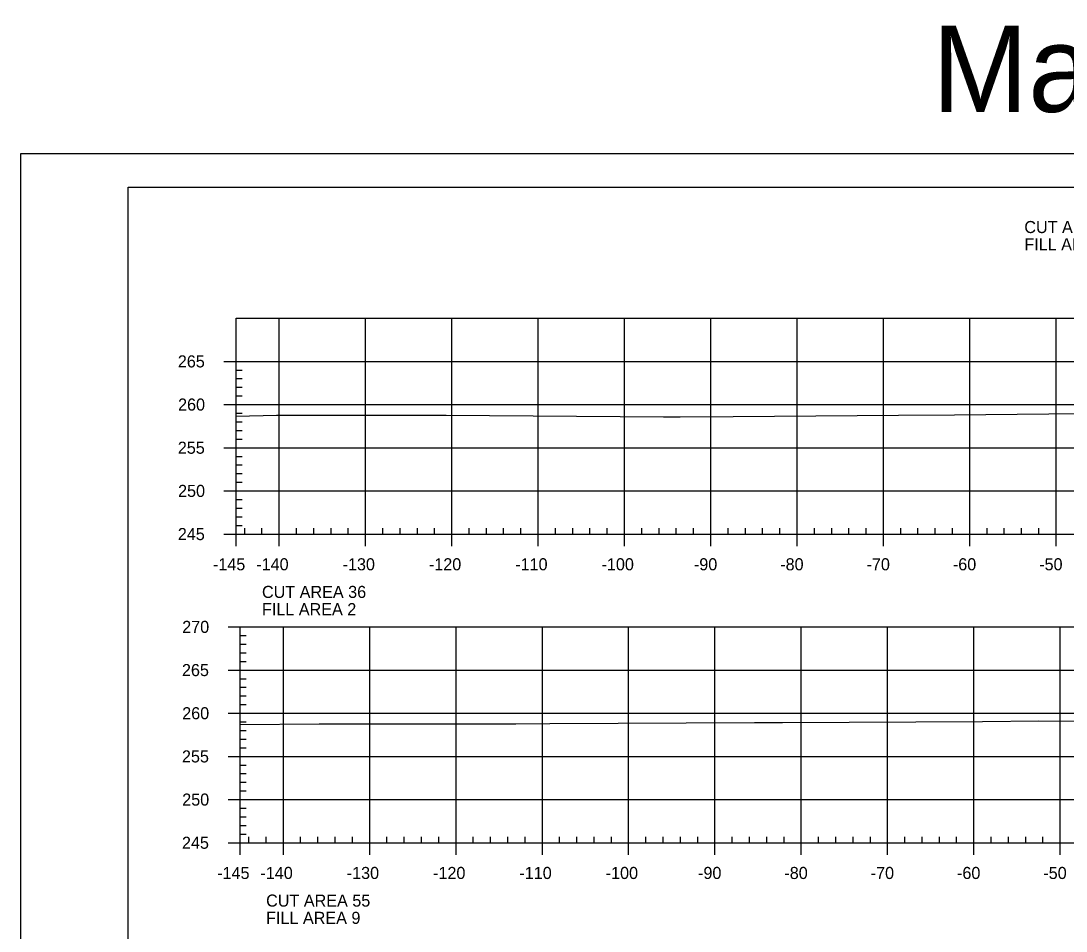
# Model space of a CAD drawing. Extents: x 1365647 to 1367999, y 387113 to 400173.
# Drawn here: x 1366507.4 to 1366628.5, y 387249 to 387354.4 of the extents above; entities that cross this region are included whole.
import ezdxf

# ---------------------------------------------------------------- set-up
doc = ezdxf.new("R2010")
doc.units = 0
for name, color, linetype in [('R_Axis', 7, 'Continuous'), ('R_Axis Annot', 7, 'Continuous'), ('R_Border', 7, 'Continuous'), ('R_Drive', 7, 'Continuous'), ('R_Exist Surface', 7, 'Continuous'), ('R_Grid', 7, 'Continuous'), ('R_No Plot', 7, 'Continuous')]:
    doc.layers.add(name, color=color, linetype=linetype)

msp = doc.modelspace()

# ---------------------------------------------------------------- linework, layer by layer
at = {"layer": 'R_Axis'}
for p, q in [((1366530.92, 387315.01), (1366532.32, 387315.01)), ((1366532.32, 387295.01), (1366532.32, 387315.01)), ((1366532.32, 387314.01), (1366533.02, 387314.01)), ((1366532.32, 387313.01), (1366533.02, 387313.01)), ((1366532.32, 387312.01), (1366533.02, 387312.01)), ((1366532.32, 387311.01), (1366533.02, 387311.01)), ((1366530.92, 387310.01), (1366532.32, 387310.01)), ((1366532.32, 387309.01), (1366533.02, 387309.01)), ((1366532.32, 387308.01), (1366533.02, 387308.01)), ((1366532.32, 387307.01), (1366533.02, 387307.01)), ((1366532.32, 387306.01), (1366533.02, 387306.01)), ((1366530.92, 387305.01), (1366532.32, 387305.01)), ((1366532.32, 387304.01), (1366533.02, 387304.01)), ((1366532.32, 387303.01), (1366533.02, 387303.01)), ((1366532.32, 387302.01), (1366533.02, 387302.01)), ((1366532.32, 387301.01), (1366533.02, 387301.01)), ((1366530.92, 387300.01), (1366532.32, 387300.01)), ((1366532.32, 387299.01), (1366533.02, 387299.01)), ((1366532.32, 387298.01), (1366533.02, 387298.01)), ((1366532.32, 387297.01), (1366533.02, 387297.01)), ((1366532.32, 387296.01), (1366533.02, 387296.01)), ((1366530.92, 387295.01), (1366532.32, 387295.01)), ((1366532.32, 387295.01), (1366532.32, 387295.71)), ((1366532.32, 387295.01), (1366822.32, 387295.01)), ((1366532.32, 387293.61), (1366532.32, 387295.01)), ((1366533.32, 387295.01), (1366533.32, 387295.71)), ((1366535.32, 387295.01), (1366535.32, 387295.71)), ((1366537.32, 387293.61), (1366537.32, 387295.01)), ((1366539.32, 387295.01), (1366539.32, 387295.71)), ((1366541.32, 387295.01), (1366541.32, 387295.71)), ((1366543.32, 387295.01), (1366543.32, 387295.71)), ((1366545.32, 387295.01), (1366545.32, 387295.71)), ((1366547.32, 387293.61), (1366547.32, 387295.01)), ((1366549.32, 387295.01), (1366549.32, 387295.71)), ((1366551.32, 387295.01), (1366551.32, 387295.71)), ((1366553.32, 387295.01), (1366553.32, 387295.71)), ((1366555.32, 387295.01), (1366555.32, 387295.71)), ((1366557.32, 387293.61), (1366557.32, 387295.01)), ((1366559.32, 387295.01), (1366559.32, 387295.71)), ((1366561.32, 387295.01), (1366561.32, 387295.71)), ((1366563.32, 387295.01), (1366563.32, 387295.71)), ((1366565.32, 387295.01), (1366565.32, 387295.71)), ((1366567.32, 387293.61), (1366567.32, 387295.01)), ((1366569.32, 387295.01), (1366569.32, 387295.71)), ((1366571.32, 387295.01), (1366571.32, 387295.71)), ((1366573.32, 387295.01), (1366573.32, 387295.71)), ((1366575.32, 387295.01), (1366575.32, 387295.71)), ((1366577.32, 387293.61), (1366577.32, 387295.01)), ((1366579.32, 387295.01), (1366579.32, 387295.71)), ((1366581.32, 387295.01), (1366581.32, 387295.71)), ((1366583.32, 387295.01), (1366583.32, 387295.71)), ((1366585.32, 387295.01), (1366585.32, 387295.71)), ((1366587.32, 387293.61), (1366587.32, 387295.01)), ((1366589.32, 387295.01), (1366589.32, 387295.71)), ((1366591.32, 387295.01), (1366591.32, 387295.71)), ((1366593.32, 387295.01), (1366593.32, 387295.71)), ((1366595.32, 387295.01), (1366595.32, 387295.71)), ((1366597.32, 387293.61), (1366597.32, 387295.01)), ((1366599.32, 387295.01), (1366599.32, 387295.71)), ((1366601.32, 387295.01), (1366601.32, 387295.71)), ((1366603.32, 387295.01), (1366603.32, 387295.71)), ((1366605.32, 387295.01), (1366605.32, 387295.71)), ((1366607.32, 387293.61), (1366607.32, 387295.01)), ((1366609.32, 387295.01), (1366609.32, 387295.71)), ((1366611.32, 387295.01), (1366611.32, 387295.71)), ((1366613.32, 387295.01), (1366613.32, 387295.71)), ((1366615.32, 387295.01), (1366615.32, 387295.71)), ((1366617.32, 387293.61), (1366617.32, 387295.01)), ((1366619.32, 387295.01), (1366619.32, 387295.71)), ((1366621.32, 387295.01), (1366621.32, 387295.71)), ((1366623.32, 387295.01), (1366623.32, 387295.71)), ((1366625.32, 387295.01), (1366625.32, 387295.71)), ((1366627.32, 387293.61), (1366627.32, 387295.01)), ((1366531.4, 387284.26), (1366532.8, 387284.26)), ((1366532.8, 387259.26), (1366532.8, 387284.26)), ((1366532.8, 387283.26), (1366533.5, 387283.26)), ((1366532.8, 387282.26), (1366533.5, 387282.26)), ((1366532.8, 387281.26), (1366533.5, 387281.26)), ((1366532.8, 387280.26), (1366533.5, 387280.26)), ((1366531.4, 387279.26), (1366532.8, 387279.26)), ((1366532.8, 387278.26), (1366533.5, 387278.26)), ((1366532.8, 387277.26), (1366533.5, 387277.26)), ((1366532.8, 387276.26), (1366533.5, 387276.26)), ((1366531.4, 387274.26), (1366532.8, 387274.26)), ((1366532.8, 387275.26), (1366533.5, 387275.26)), ((1366532.8, 387273.26), (1366533.5, 387273.26)), ((1366532.8, 387272.26), (1366533.5, 387272.26)), ((1366532.8, 387271.26), (1366533.5, 387271.26)), ((1366532.8, 387270.26), (1366533.5, 387270.26)), ((1366531.4, 387269.26), (1366532.8, 387269.26)), ((1366532.8, 387268.26), (1366533.5, 387268.26)), ((1366532.8, 387267.26), (1366533.5, 387267.26)), ((1366532.8, 387266.26), (1366533.5, 387266.26)), ((1366532.8, 387265.26), (1366533.5, 387265.26)), ((1366531.4, 387264.26), (1366532.8, 387264.26)), ((1366532.8, 387263.26), (1366533.5, 387263.26)), ((1366532.8, 387262.26), (1366533.5, 387262.26)), ((1366532.8, 387261.26), (1366533.5, 387261.26)), ((1366532.8, 387260.26), (1366533.5, 387260.26)), ((1366532.8, 387259.26), (1366532.8, 387259.96)), ((1366533.8, 387259.26), (1366533.8, 387259.96)), ((1366535.8, 387259.26), (1366535.8, 387259.96)), ((1366539.8, 387259.26), (1366539.8, 387259.96)), ((1366541.8, 387259.26), (1366541.8, 387259.96)), ((1366543.8, 387259.26), (1366543.8, 387259.96)), ((1366545.8, 387259.26), (1366545.8, 387259.96)), ((1366549.8, 387259.26), (1366549.8, 387259.96)), ((1366551.8, 387259.26), (1366551.8, 387259.96)), ((1366553.8, 387259.26), (1366553.8, 387259.96)), ((1366555.8, 387259.26), (1366555.8, 387259.96)), ((1366559.8, 387259.26), (1366559.8, 387259.96)), ((1366561.8, 387259.26), (1366561.8, 387259.96)), ((1366563.8, 387259.26), (1366563.8, 387259.96)), ((1366565.8, 387259.26), (1366565.8, 387259.96)), ((1366569.8, 387259.26), (1366569.8, 387259.96)), ((1366571.8, 387259.26), (1366571.8, 387259.96)), ((1366573.8, 387259.26), (1366573.8, 387259.96)), ((1366575.8, 387259.26), (1366575.8, 387259.96)), ((1366579.8, 387259.26), (1366579.8, 387259.96)), ((1366581.8, 387259.26), (1366581.8, 387259.96)), ((1366583.8, 387259.26), (1366583.8, 387259.96)), ((1366585.8, 387259.26), (1366585.8, 387259.96)), ((1366589.8, 387259.26), (1366589.8, 387259.96)), ((1366591.8, 387259.26), (1366591.8, 387259.96)), ((1366593.8, 387259.26), (1366593.8, 387259.96)), ((1366595.8, 387259.26), (1366595.8, 387259.96)), ((1366599.8, 387259.26), (1366599.8, 387259.96)), ((1366601.8, 387259.26), (1366601.8, 387259.96)), ((1366603.8, 387259.26), (1366603.8, 387259.96)), ((1366605.8, 387259.26), (1366605.8, 387259.96)), ((1366609.8, 387259.26), (1366609.8, 387259.96)), ((1366611.8, 387259.26), (1366611.8, 387259.96)), ((1366613.8, 387259.26), (1366613.8, 387259.96)), ((1366615.8, 387259.26), (1366615.8, 387259.96)), ((1366619.8, 387259.26), (1366619.8, 387259.96)), ((1366621.8, 387259.26), (1366621.8, 387259.96)), ((1366623.8, 387259.26), (1366623.8, 387259.96)), ((1366625.8, 387259.26), (1366625.8, 387259.96)), ((1366531.4, 387259.26), (1366532.8, 387259.26)), ((1366532.8, 387259.26), (1366822.8, 387259.26)), ((1366532.8, 387257.86), (1366532.8, 387259.26)), ((1366537.8, 387257.86), (1366537.8, 387259.26)), ((1366547.8, 387257.86), (1366547.8, 387259.26)), ((1366557.8, 387257.86), (1366557.8, 387259.26)), ((1366567.8, 387257.86), (1366567.8, 387259.26)), ((1366577.8, 387257.86), (1366577.8, 387259.26)), ((1366587.8, 387257.86), (1366587.8, 387259.26)), ((1366597.8, 387257.86), (1366597.8, 387259.26)), ((1366607.8, 387257.86), (1366607.8, 387259.26)), ((1366617.8, 387257.86), (1366617.8, 387259.26)), ((1366627.8, 387257.86), (1366627.8, 387259.26))]:
    msp.add_line(p, q, dxfattribs=at)
at = {"layer": 'R_Border'}
for p, q in [((1366519.8, 387335.17), (1366835.98, 387335.17)), ((1366519.8, 387129.71), (1366519.8, 387335.17))]:
    msp.add_line(p, q, dxfattribs=at)
at = {"layer": 'R_Exist Surface'}
for points in [[(1366532.32, 387308.68), (1366537.02, 387308.77), (1366555.43, 387308.77), (1366556.37, 387308.77), (1366556.66, 387308.77), (1366581.84, 387308.58), (1366583.77, 387308.58), (1366589.89, 387308.62), (1366609.07, 387308.77), (1366615.54, 387308.82), (1366633.73, 387309)], [(1366532.8, 387272.95), (1366541.95, 387273.02), (1366545.97, 387273.02), (1366554.76, 387273.03), (1366564.73, 387273.02), (1366568.66, 387273.08), (1366592.39, 387273.19), (1366595.63, 387273.18), (1366618.81, 387273.29), (1366625.33, 387273.36), (1366631.89, 387273.35)]]:
    msp.add_lwpolyline(points, dxfattribs=at)
at = {"layer": 'R_Grid'}
for p, q in [((1366532.32, 387320.01), (1366822.32, 387320.01)), ((1366532.32, 387295.01), (1366532.32, 387320.01)), ((1366537.32, 387295.01), (1366537.32, 387320.01)), ((1366547.32, 387295.01), (1366547.32, 387320.01)), ((1366557.32, 387295.01), (1366557.32, 387320.01)), ((1366567.32, 387295.01), (1366567.32, 387320.01)), ((1366577.32, 387295.01), (1366577.32, 387320.01)), ((1366587.32, 387295.01), (1366587.32, 387320.01)), ((1366597.32, 387295.01), (1366597.32, 387320.01)), ((1366607.32, 387295.01), (1366607.32, 387320.01)), ((1366617.32, 387295.01), (1366617.32, 387320.01)), ((1366627.32, 387295.01), (1366627.32, 387320.01)), ((1366532.32, 387315.01), (1366822.32, 387315.01)), ((1366532.32, 387310.01), (1366822.32, 387310.01)), ((1366532.32, 387305.01), (1366822.32, 387305.01)), ((1366532.32, 387300.01), (1366822.32, 387300.01)), ((1366532.32, 387295.01), (1366822.32, 387295.01)), ((1366532.8, 387284.26), (1366822.8, 387284.26)), ((1366532.8, 387259.26), (1366532.8, 387284.26)), ((1366537.8, 387259.26), (1366537.8, 387284.26)), ((1366547.8, 387259.26), (1366547.8, 387284.26)), ((1366557.8, 387259.26), (1366557.8, 387284.26)), ((1366567.8, 387259.26), (1366567.8, 387284.26)), ((1366577.8, 387259.26), (1366577.8, 387284.26)), ((1366587.8, 387259.26), (1366587.8, 387284.26)), ((1366597.8, 387259.26), (1366597.8, 387284.26)), ((1366607.8, 387259.26), (1366607.8, 387284.26)), ((1366617.8, 387259.26), (1366617.8, 387284.26)), ((1366627.8, 387259.26), (1366627.8, 387284.26)), ((1366532.8, 387279.26), (1366822.8, 387279.26)), ((1366532.8, 387274.26), (1366822.8, 387274.26)), ((1366532.8, 387269.26), (1366822.8, 387269.26)), ((1366532.8, 387264.26), (1366822.8, 387264.26)), ((1366532.8, 387259.26), (1366822.8, 387259.26))]:
    msp.add_line(p, q, dxfattribs=at)
at = {"layer": 'R_No Plot'}
msp.add_line((1366507.4, 387339.07), (1366840.73, 387339.07), dxfattribs=at)
msp.add_lwpolyline([(1366507.39, 387339.07), (1366840.73, 387339.07), (1366840.73, 387125.73), (1366507.39, 387125.73)], close=True, dxfattribs=at)

# ---------------------------------------------------------------- texts
at = {"layer": 'R_Axis Annot'}
for s, p in [('CUT AREA 36', (1366623.64, 387329.87)), ('FILL AREA 2', (1366623.64, 387327.87)), ('265', (1366525.57, 387314.31)), ('260', (1366525.6, 387309.31)), ('255', (1366525.57, 387304.31)), ('250', (1366525.6, 387299.31)), ('245', (1366525.57, 387294.31)), ('-145', (1366529.64, 387290.81)), ('-140', (1366534.66, 387290.81)), ('-130', (1366544.66, 387290.81)), ('-120', (1366554.66, 387290.81)), ('-110', (1366564.66, 387290.81)), ('-100', (1366574.66, 387290.81)), ('-90', (1366585.36, 387290.81)), ('-80', (1366595.36, 387290.81)), ('-70', (1366605.36, 387290.81)), ('-60', (1366615.36, 387290.81)), ('-50', (1366625.36, 387290.81)), ('CUT AREA 36', (1366535.32, 387287.61)), ('FILL AREA 2', (1366535.32, 387285.61)), ('270', (1366526.08, 387283.56)), ('265', (1366526.05, 387278.56)), ('260', (1366526.08, 387273.56)), ('255', (1366526.05, 387268.56)), ('250', (1366526.08, 387263.56)), ('245', (1366526.05, 387258.56)), ('-145', (1366530.13, 387255.06)), ('-140', (1366535.14, 387255.06)), ('-130', (1366545.14, 387255.06)), ('-120', (1366555.14, 387255.06)), ('-110', (1366565.14, 387255.06)), ('-100', (1366575.14, 387255.06)), ('-90', (1366585.84, 387255.06)), ('-80', (1366595.84, 387255.06)), ('-70', (1366605.84, 387255.06)), ('-60', (1366615.84, 387255.06)), ('-50', (1366625.84, 387255.06)), ('CUT AREA 55', (1366535.8, 387251.86)), ('FILL AREA 9', (1366535.8, 387249.86))]:
    msp.add_text(s, height=1.4, dxfattribs=at).set_placement(p)
at = {"layer": 'R_Drive'}
msp.add_text('Marvin Fisher', height=10, rotation=360, dxfattribs=at).set_placement((1366612.96, 387343.91))
at = {"layer": 'R_No Plot'}
for p in [(1366541.9, 387272.97), (1366568.62, 387273.03), (1366595.59, 387273.13), (1366625.29, 387273.31)]:
    msp.add_text('+', height=0.1, dxfattribs=at).set_placement(p)

doc.saveas('drawing.dxf')
